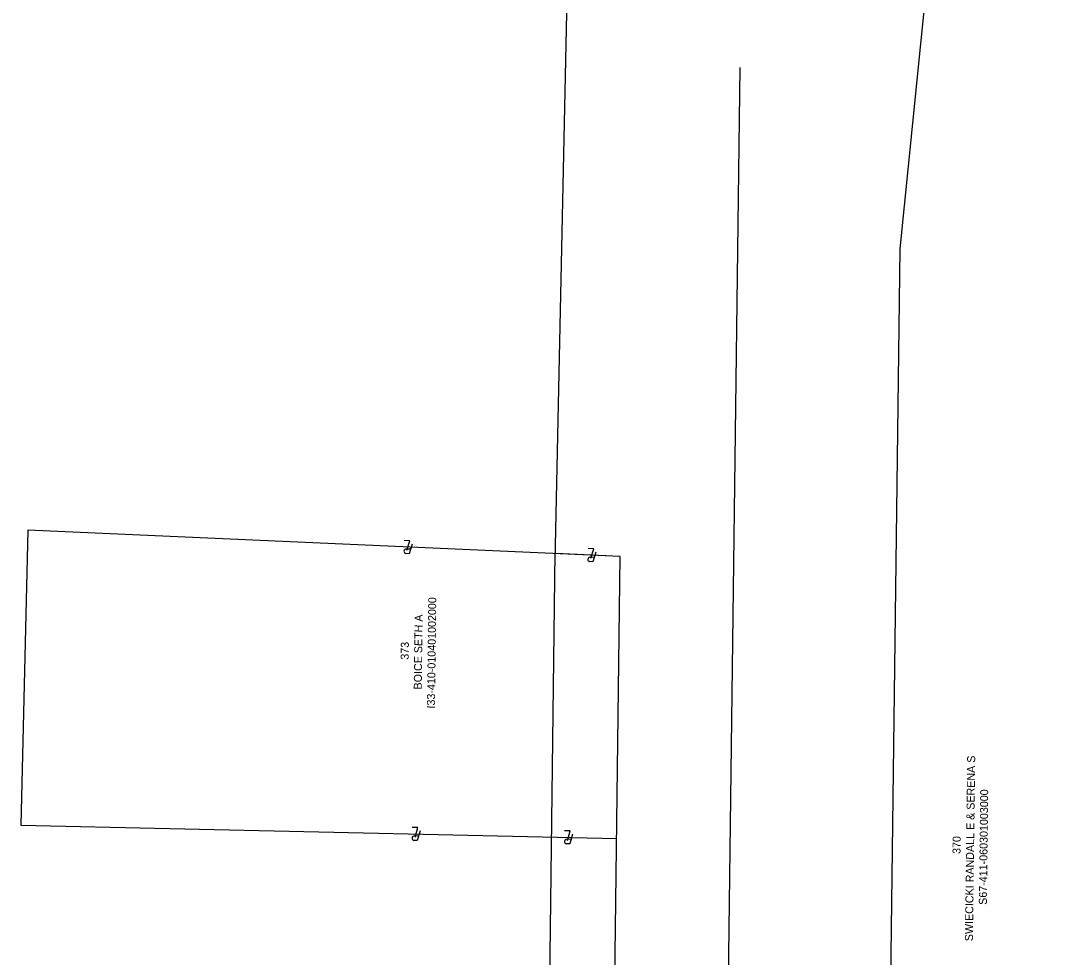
# Model space of a CAD drawing. Extents: x 1652206 to 1653153, y 604222 to 614600.
# Drawn here: x 1652353.7 to 1652675.8, y 608541.6 to 608829.9 of the extents above; entities that cross this region are included whole.
import ezdxf

# ---------------------------------------------------------------- set-up
doc = ezdxf.new("R2010")
doc.units = 0
for name, color, linetype in [('_CIVIL_CONSTRUCTION', 7, 'Continuous'), ('Default', 7, 'Continuous'), ('DT_X_Contour_Minor', 7, 'Continuous'), ('GE_P_Alignment_100_Bearings', 7, 'Continuous'), ('GE_P_Alignment_100_Cardinal_Points', 7, 'Continuous'), ('GE_P_Alignment_100_Distances', 7, 'Continuous')]:
    doc.layers.add(name, color=color, linetype=linetype)

msp = doc.modelspace()

# ---------------------------------------------------------------- linework, layer by layer
at = {"layer": '_CIVIL_CONSTRUCTION'}
msp.add_line((1652550.86, 606872.07), (1652575.14, 608815.48), dxfattribs=at)
at = {"layer": 'DT_X_Contour_Minor'}
msp.add_lwpolyline([(1652527.01, 607765.18), (1652507.01, 607765.43), (1652518.27, 608666.13)], dxfattribs=at)
at = {"layer": 'GE_P_Alignment_100_Bearings'}
for p, q in [((1652355.84, 608672.98), (1652353.72, 608582.18)), ((1652538.25, 608664.92), (1652355.84, 608672.98)), ((1652473.66, 608667.15), (1652472.37, 608667.21)), ((1652472.89, 608667.81), (1652472.89, 608667.81)), ((1652530.26, 608664.64), (1652528.97, 608664.7)), ((1652529.49, 608665.3), (1652529.49, 608665.3)), ((1652353.72, 608582.18), (1652537.17, 608578.1)), ((1652476.16, 608578.84), (1652474.86, 608578.87)), ((1652475.37, 608579.48), (1652475.37, 608579.48)), ((1652523.09, 608577.79), (1652521.79, 608577.82)), ((1652522.3, 608578.43), (1652522.3, 608578.43))]:
    msp.add_line(p, q, dxfattribs=at)
for points in [[(1652472.58, 608666.86), (1652473.5, 608669.78), (1652471.76, 608669.85)], [(1652474.15, 608668.72), (1652473.24, 608665.79), (1652472.21, 608665.84)], [(1652529.18, 608664.36), (1652530.1, 608667.27), (1652528.35, 608667.35)], [(1652530.75, 608666.22), (1652529.84, 608663.29), (1652528.81, 608663.34)], [(1652475.08, 608578.52), (1652475.94, 608581.46), (1652474.19, 608581.5)], [(1652476.61, 608580.42), (1652475.77, 608577.47), (1652474.73, 608577.5)], [(1652522.01, 608577.48), (1652522.87, 608580.42), (1652521.12, 608580.46)], [(1652523.54, 608579.37), (1652522.69, 608576.43), (1652521.66, 608576.45)]]:
    msp.add_lwpolyline(points, dxfattribs=at)
for centre, start, end in [((1652472.34, 608666.52), 87.9388, 258.7959), ((1652528.94, 608664.01), 87.9388, 258.7959), ((1652474.85, 608578.18), 89.197, 260.0541), ((1652521.78, 608577.13), 89.197, 260.0541)]:
    msp.add_arc(centre, 0.69, start, end, dxfattribs=at)
at = {"layer": 'GE_P_Alignment_100_Distances'}
for p, q in [((1652518.23, 608663.5), (1652542.27, 609782.55)), ((1652624.44, 608759.7), (1652675.85, 609272.18)), ((1652621.47, 608521.72), (1652624.44, 608759.7)), ((1652538.25, 608664.92), (1652518.28, 608665.8)), ((1652525.46, 607640.72), (1652538.25, 608664.92))]:
    msp.add_line(p, q, dxfattribs=at)

# ---------------------------------------------------------------- texts
at = {"layer": 'Default'}
for s, height, p in [('I33-410-010401002000', 2.4653, (1652481.19, 608618.09)), ('BOICE SETH A', 2.4653, (1652477.14, 608623.95)), ('373', 2.465, (1652473.11, 608633.12))]:
    msp.add_text(s, height=height, rotation=89.2843, dxfattribs=at).set_placement(p)
at = {"layer": 'GE_P_Alignment_100_Cardinal_Points'}
for s, height, p in [('SWIECICKI RANDALL E & SERENA S', 2.4653, (1652646.85, 608546.43)), ('S67-411-060301003000', 2.4653, (1652651.14, 608557.63)), ('370', 2.465, (1652643.03, 608573.3))]:
    msp.add_text(s, height=height, rotation=89.2843, dxfattribs=at).set_placement(p)

doc.saveas('drawing.dxf')
